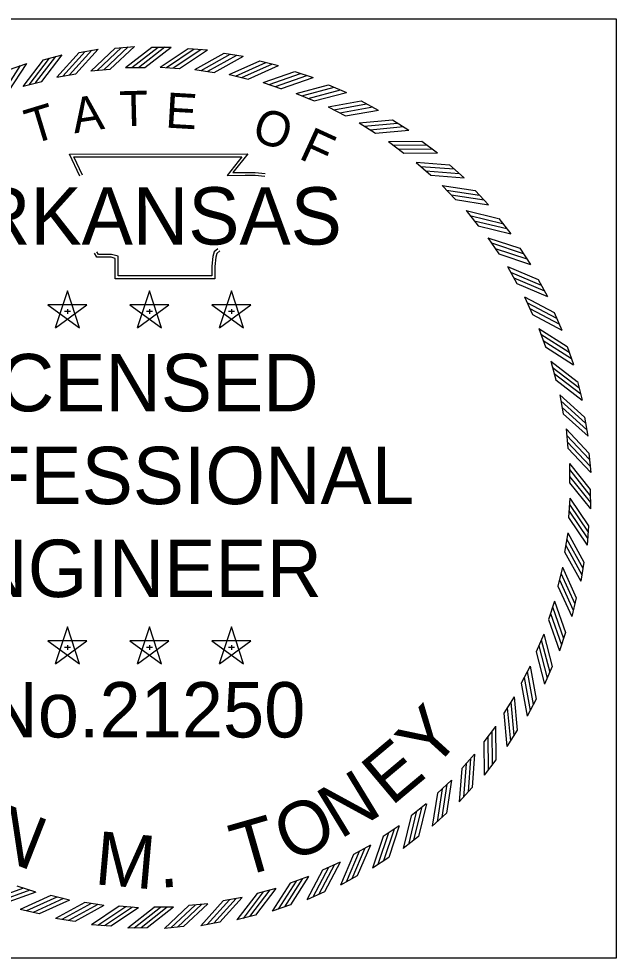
# Model space of a CAD drawing. Extents: x 0 to 1228740, y 0 to 152440.
# Drawn here: x 35.456 to 37.204, y 22.732 to 25.482 of the extents above; entities that cross this region are included whole.
import ezdxf

# ---------------------------------------------------------------- set-up
doc = ezdxf.new("R2010")
doc.units = 0
doc.layers.add('STAMP_JMT', color=7, linetype='Continuous')

msp = doc.modelspace()

# ---------------------------------------------------------------- linework, layer by layer
at = {"layer": 'STAMP_JMT'}
for p, q in [((35.6326, 25.3832), (35.6883, 25.3931)), ((35.7384, 25.3959), (35.7948, 25.4011)), ((35.8455, 25.399), (35.9021, 25.399)), ((35.9515, 25.3948), (36.0079, 25.3907)), ((35.5282, 25.3619), (35.5829, 25.3763)), ((36.0572, 25.3811), (36.113, 25.3723)), ((36.1614, 25.3587), (36.2163, 25.3453)), ((35.4258, 25.332), (35.4792, 25.3509)), ((35.6671, 25.3289), (35.7236, 25.3341)), ((35.7684, 25.3389), (35.825, 25.3389)), ((35.8701, 25.3405), (35.9266, 25.3363)), ((35.9716, 25.3336), (36.0276, 25.3248)), ((36.2634, 25.3277), (36.317, 25.3099)), ((35.5671, 25.3106), (35.6229, 25.3204)), ((36.0722, 25.3185), (36.1272, 25.3051)), ((35.4688, 25.2841), (35.5237, 25.2985)), ((36.1712, 25.295), (36.2249, 25.2771)), ((36.3625, 25.2885), (36.4145, 25.2662)), ((36.2679, 25.2635), (36.32, 25.2412)), ((36.3617, 25.2241), (36.4118, 25.1976)), ((36.458, 25.2412), (36.508, 25.2147)), ((36.4519, 25.1771), (36.4996, 25.1465)), ((36.5493, 25.1861), (36.5969, 25.1557)), ((36.5379, 25.1228), (36.583, 25.0884)), ((36.6358, 25.1238), (36.6807, 25.0894)), ((36.6191, 25.0615), (36.6612, 25.0235)), ((36.7167, 25.0545), (36.7587, 25.0165)), ((36.6951, 24.9938), (36.7338, 24.9525)), ((36.7917, 24.9787), (36.8304, 24.9374)), ((36.7651, 24.9201), (36.8003, 24.8757)), ((36.8602, 24.897), (36.8954, 24.8527)), ((36.8288, 24.8408), (36.8603, 24.7936)), ((36.9217, 24.8099), (36.9531, 24.7629)), ((36.8858, 24.7565), (36.9132, 24.7069)), ((36.9758, 24.7181), (37.0032, 24.6686)), ((35.5984, 24.6856), (35.563, 24.577)), ((35.6337, 24.5771), (35.5985, 24.6857)), ((35.8383, 24.6856), (35.8029, 24.577)), ((35.8735, 24.5771), (35.8384, 24.6857)), ((36.0782, 24.6856), (36.0428, 24.577)), ((36.1134, 24.5771), (36.0782, 24.6857)), ((36.9356, 24.6678), (36.9589, 24.6161)), ((35.6555, 24.6441), (35.5413, 24.6442)), ((35.5414, 24.6441), (35.6337, 24.5769)), ((35.5632, 24.5771), (35.6556, 24.6441)), ((35.8953, 24.6441), (35.7812, 24.6442)), ((35.7813, 24.6441), (35.8736, 24.5769)), ((35.803, 24.5771), (35.8955, 24.6441)), ((36.1352, 24.6441), (36.021, 24.6442)), ((36.0211, 24.6441), (36.1134, 24.5769)), ((36.0429, 24.5771), (36.1353, 24.6441)), ((35.5903, 24.6259), (35.6073, 24.6259)), ((35.5985, 24.632), (35.5985, 24.6177)), ((35.8302, 24.6259), (35.8471, 24.6259)), ((35.8384, 24.632), (35.8384, 24.6177)), ((36.07, 24.6259), (36.087, 24.6259)), ((36.0783, 24.632), (36.0783, 24.6177)), ((37.0221, 24.6221), (37.0453, 24.5705)), ((36.9779, 24.5753), (36.9968, 24.5218)), ((37.0604, 24.5226), (37.0792, 24.4693)), ((37.0124, 24.4796), (37.0269, 24.4248)), ((37.0903, 24.4203), (37.1047, 24.3656)), ((37.039, 24.3814), (37.0488, 24.3255)), ((37.1116, 24.3158), (37.1214, 24.2601)), ((37.0573, 24.2813), (37.0625, 24.2249)), ((37.1243, 24.21), (37.1295, 24.1537)), ((37.0672, 24.1801), (37.0678, 24.1234)), ((37.1281, 24.1034), (37.1286, 24.0469)), ((37.0688, 24.0783), (37.0647, 24.0218)), ((37.1232, 23.997), (37.119, 23.9406)), ((37.062, 23.9768), (37.0532, 23.9208)), ((37.0468, 23.8763), (37.0334, 23.8212)), ((37.1095, 23.8913), (37.1007, 23.8354)), ((37.0234, 23.7773), (37.0055, 23.7235)), ((37.087, 23.787), (37.0737, 23.7321)), ((35.5984, 23.7021), (35.563, 23.5935)), ((35.6337, 23.5936), (35.5985, 23.7022)), ((35.8383, 23.7021), (35.8029, 23.5935)), ((35.8735, 23.5936), (35.8384, 23.7022)), ((36.0782, 23.7021), (36.0428, 23.5935)), ((36.1134, 23.5936), (36.0782, 23.7022)), ((36.9919, 23.6805), (36.9696, 23.6284)), ((37.0561, 23.685), (37.0382, 23.6314)), ((35.6555, 23.6606), (35.5413, 23.6607)), ((35.5414, 23.6606), (35.6337, 23.5934)), ((35.5632, 23.5936), (35.6556, 23.6606)), ((35.8953, 23.6606), (35.7812, 23.6607)), ((35.7813, 23.6606), (35.8736, 23.5934)), ((35.803, 23.5936), (35.8955, 23.6606)), ((36.1352, 23.6606), (36.021, 23.6607)), ((36.0211, 23.6606), (36.1134, 23.5934)), ((36.0429, 23.5936), (36.1353, 23.6606)), ((35.5903, 23.6424), (35.6073, 23.6424)), ((35.5985, 23.6485), (35.5985, 23.6341)), ((35.8302, 23.6424), (35.8471, 23.6424)), ((35.8384, 23.6485), (35.8384, 23.6341)), ((36.07, 23.6424), (36.087, 23.6424)), ((36.0783, 23.6485), (36.0783, 23.6341)), ((36.9525, 23.5868), (36.9259, 23.5367)), ((37.0169, 23.5859), (36.9946, 23.5339)), ((36.9054, 23.4965), (36.8749, 23.4488)), ((36.9695, 23.4904), (36.9431, 23.4404)), ((36.8511, 23.4105), (36.8167, 23.3655)), ((36.9145, 23.3991), (36.884, 23.3515)), ((36.7899, 23.3293), (36.7519, 23.2872)), ((36.8521, 23.3127), (36.8178, 23.2677)), ((36.7222, 23.2534), (36.6808, 23.2146)), ((36.7828, 23.2317), (36.7449, 23.1897)), ((36.6484, 23.1833), (36.604, 23.1481)), ((36.7071, 23.1567), (36.6658, 23.118)), ((36.5691, 23.1196), (36.522, 23.0881)), ((36.6254, 23.0882), (36.5811, 23.0531)), ((36.4849, 23.0626), (36.4353, 23.0352)), ((36.5383, 23.0267), (36.4912, 22.9953)), ((36.3962, 23.0128), (36.3445, 22.9896)), ((36.3036, 22.9705), (36.2502, 22.9516)), ((36.4465, 22.9726), (36.397, 22.9452)), ((35.5056, 22.925), (35.4518, 22.9429)), ((36.2079, 22.936), (36.1531, 22.9216)), ((35.6046, 22.9016), (35.5495, 22.915)), ((36.1097, 22.9095), (36.0539, 22.8996)), ((36.3504, 22.9263), (36.2989, 22.9031)), ((35.7052, 22.8864), (35.6492, 22.8952)), ((35.8067, 22.8796), (35.7502, 22.8838)), ((35.9084, 22.8812), (35.8517, 22.8807)), ((36.0097, 22.8912), (35.9532, 22.886)), ((36.2509, 22.888), (36.1976, 22.8692)), ((35.5154, 22.8614), (35.4605, 22.8748)), ((36.1486, 22.8581), (36.0939, 22.8438)), ((35.6196, 22.839), (35.5638, 22.8478)), ((35.7253, 22.8252), (35.6689, 22.8294)), ((36.0442, 22.8368), (35.9885, 22.827)), ((35.8318, 22.8203), (35.7753, 22.8198)), ((35.9383, 22.8242), (35.882, 22.819))]:
    msp.add_line(p, q, dxfattribs=at)
msp.add_lwpolyline([(34.454, 25.4817), (37.204, 25.4817), (37.204, 22.7317), (34.454, 22.7317)], close=True, dxfattribs=at)
for points in [[(35.567, 25.3105), (35.6325, 25.3832)], [(35.585, 25.3135), (35.6505, 25.3862)], [(35.6042, 25.3174), (35.6698, 25.39)], [(35.6228, 25.3205), (35.6883, 25.3931)], [(35.6671, 25.3288), (35.7384, 25.3958)], [(35.6852, 25.3303), (35.7565, 25.3973)], [(35.7047, 25.3326), (35.776, 25.3996)], [(35.7235, 25.3341), (35.7948, 25.4011)], [(35.7683, 25.3388), (35.8455, 25.399)], [(35.7865, 25.3387), (35.8637, 25.3988)], [(35.8061, 25.3391), (35.8833, 25.3993)], [(35.825, 25.3389), (35.9021, 25.3991)], [(35.87, 25.3404), (35.9514, 25.3948)], [(35.8881, 25.3389), (35.9695, 25.3933)], [(35.9078, 25.3379), (35.9891, 25.3922)], [(35.9265, 25.3363), (36.0079, 25.3907)], [(35.4688, 25.284), (35.5281, 25.3618)], [(35.4864, 25.2885), (35.5457, 25.3663)], [(35.5053, 25.2939), (35.5646, 25.3717)], [(35.5236, 25.2985), (35.5829, 25.3763)], [(35.9715, 25.3336), (36.0571, 25.381)], [(35.9895, 25.3306), (36.075, 25.378)], [(36.0089, 25.328), (36.0945, 25.3754)], [(36.0275, 25.3249), (36.1131, 25.3723)], [(36.0721, 25.3184), (36.1613, 25.3586)], [(35.4087, 25.2623), (35.4614, 25.3448)], [(35.4265, 25.2685), (35.4792, 25.3509)], [(36.0897, 25.314), (36.1789, 25.3542)], [(36.1089, 25.3097), (36.1981, 25.35)], [(36.1272, 25.3051), (36.2164, 25.3453)], [(36.1711, 25.295), (36.2633, 25.3277)], [(36.1883, 25.2891), (36.2805, 25.3218)], [(36.2071, 25.2833), (36.2993, 25.316)], [(36.2249, 25.2772), (36.3171, 25.3099)], [(36.2678, 25.2635), (36.3624, 25.2885)], [(36.2845, 25.2562), (36.3791, 25.2812)], [(36.3027, 25.2488), (36.3973, 25.2738)], [(36.32, 25.2413), (36.4146, 25.2663)], [(36.3616, 25.2241), (36.4579, 25.2412)], [(36.3776, 25.2154), (36.4739, 25.2325)], [(36.3952, 25.2066), (36.4915, 25.2237)], [(36.4117, 25.1976), (36.5081, 25.2147)], [(36.4518, 25.1771), (36.5492, 25.1861)], [(36.467, 25.1671), (36.5645, 25.1762)], [(36.4838, 25.1569), (36.5812, 25.166)], [(36.4996, 25.1466), (36.597, 25.1557)], [(36.5378, 25.1228), (36.6357, 25.1238)], [(36.5522, 25.1116), (36.65, 25.1126)], [(35.6348, 25.0206), (35.6047, 25.0858), (36.1262, 25.0862), (36.0827, 25.0314), (36.1181, 25.0319), (36.1477, 25.0322), (36.1773, 25.029)], [(36.5681, 25.1), (36.6659, 25.101)], [(36.5829, 25.0884), (36.6808, 25.0894)], [(35.6423, 25.024), (35.6176, 25.0776), (36.1091, 25.0779), (36.0654, 25.0229), (36.1182, 25.0236), (36.1473, 25.024), (36.1764, 25.0208)], [(36.6191, 25.0616), (36.7167, 25.0545)], [(36.6325, 25.0492), (36.73, 25.0421)], [(36.6473, 25.0364), (36.7449, 25.0293)], [(36.6612, 25.0236), (36.7588, 25.0165)], [(36.695, 24.9938), (36.7916, 24.9787)], [(36.7073, 24.9804), (36.804, 24.9653)], [(36.7211, 24.9664), (36.8177, 24.9513)], [(36.7338, 24.9526), (36.8305, 24.9374)], [(36.765, 24.9201), (36.8601, 24.897)], [(36.7762, 24.9057), (36.8713, 24.8827)], [(36.7888, 24.8906), (36.8839, 24.8675)], [(36.8003, 24.8757), (36.8954, 24.8527)], [(36.8288, 24.8408), (36.9216, 24.81)], [(36.0388, 24.8084), (36.0279, 24.7995), (36.0241, 24.7855), (36.021, 24.7574), (36.021, 24.7291), (35.7464, 24.7291), (35.7464, 24.7695), (35.7464, 24.7865), (35.7275, 24.7922), (35.6894, 24.7922), (35.6845, 24.7997)], [(36.8387, 24.8256), (36.9316, 24.7947)], [(36.85, 24.8095), (36.9428, 24.7786)], [(36.0441, 24.802), (36.0352, 24.7948), (36.0322, 24.784), (36.0293, 24.7569), (36.0293, 24.7209), (35.7381, 24.7209), (35.7381, 24.7695), (35.7381, 24.7803), (35.7263, 24.784), (35.6849, 24.784), (35.6775, 24.7952)], [(36.8603, 24.7937), (36.9531, 24.7629)], [(36.8857, 24.7565), (36.9757, 24.7181)], [(36.8944, 24.7405), (36.9844, 24.7021)], [(36.9043, 24.7235), (36.9943, 24.6851)], [(36.9132, 24.707), (37.0032, 24.6686)], [(36.9355, 24.6678), (37.0221, 24.6221)], [(36.9428, 24.6512), (37.0294, 24.6055)], [(36.9513, 24.6334), (37.0378, 24.5877)], [(36.9589, 24.6162), (37.0454, 24.5705)], [(36.9778, 24.5753), (37.0603, 24.5226)], [(36.9838, 24.5581), (37.0662, 24.5054)], [(36.9907, 24.5397), (37.0732, 24.487)], [(36.9968, 24.5219), (37.0793, 24.4692)], [(37.0124, 24.4796), (37.0902, 24.4203)], [(37.0168, 24.462), (37.0947, 24.4027)], [(37.0223, 24.4431), (37.1001, 24.3838)], [(37.0269, 24.4248), (37.1047, 24.3655)], [(37.0389, 24.3814), (37.1116, 24.3159)], [(37.0419, 24.3635), (37.1145, 24.2979)], [(37.0457, 24.3442), (37.1184, 24.2787)], [(37.0488, 24.3256), (37.1215, 24.2601)], [(37.0572, 24.2814), (37.1242, 24.21)], [(37.0587, 24.2632), (37.1257, 24.1919)], [(37.0609, 24.2437), (37.1279, 24.1724)], [(37.0625, 24.2249), (37.1295, 24.1536)], [(37.0672, 24.1801), (37.1281, 24.1035)], [(37.0672, 24.1619), (37.1281, 24.0853)], [(37.0678, 24.1423), (37.1287, 24.0657)], [(37.0678, 24.1234), (37.1287, 24.0468)], [(37.0688, 24.0784), (37.1231, 23.997)], [(37.0663, 24.0407), (37.1206, 23.9593)], [(37.0673, 24.0603), (37.1216, 23.9789)], [(37.0647, 24.0219), (37.1191, 23.9405)], [(37.059, 23.959), (37.1064, 23.8734)], [(37.062, 23.9769), (37.1094, 23.8913)], [(37.0563, 23.9395), (37.1038, 23.8539)], [(37.0532, 23.9209), (37.1007, 23.8353)], [(37.0468, 23.8763), (37.087, 23.7871)], [(37.0423, 23.8587), (37.0825, 23.7695)], [(37.0335, 23.8212), (37.0737, 23.732)], [(37.0381, 23.8395), (37.0783, 23.7503)], [(37.0175, 23.7601), (37.0502, 23.6679)], [(37.0234, 23.7773), (37.0561, 23.6851)], [(37.0117, 23.7413), (37.0444, 23.6491)], [(37.0055, 23.7235), (37.0383, 23.6313)], [(36.9919, 23.6806), (37.0168, 23.586)], [(36.9845, 23.664), (37.0095, 23.5693)], [(36.9696, 23.6285), (36.9946, 23.5339)], [(36.9772, 23.6457), (37.0022, 23.5511)], [(36.9438, 23.5708), (36.9609, 23.4745)], [(36.9525, 23.5868), (36.9695, 23.4905)], [(36.935, 23.5533), (36.9521, 23.4569)], [(36.926, 23.5367), (36.9431, 23.4404)], [(36.9054, 23.4966), (36.9145, 23.3992)], [(36.8853, 23.4646), (36.8943, 23.3672)], [(36.8955, 23.4814), (36.9046, 23.384)], [(36.875, 23.4488), (36.884, 23.3514)], [(36.8511, 23.4106), (36.8521, 23.3128)], [(36.8284, 23.3804), (36.8294, 23.2825)], [(36.84, 23.3962), (36.841, 23.2984)], [(36.8168, 23.3655), (36.8178, 23.2677)], [(36.7899, 23.3294), (36.7828, 23.2318)], [(36.7647, 23.3011), (36.7577, 23.2035)], [(36.7776, 23.316), (36.7705, 23.2184)], [(36.752, 23.2872), (36.7449, 23.1897)], [(36.7088, 23.2411), (36.6937, 23.1444)], [(36.7222, 23.2534), (36.7071, 23.1568)], [(36.6809, 23.2146), (36.6658, 23.1179)], [(36.6948, 23.2274), (36.6797, 23.1307)], [(36.6485, 23.1834), (36.6254, 23.0883)], [(36.619, 23.1597), (36.5959, 23.0646)], [(36.6341, 23.1722), (36.611, 23.0771)], [(36.6041, 23.1481), (36.5811, 23.053)], [(36.5539, 23.1097), (36.5231, 23.0168)], [(36.5692, 23.1197), (36.5383, 23.0268)], [(36.5221, 23.0881), (36.4912, 22.9953)], [(36.5378, 23.0985), (36.507, 23.0056)], [(36.4689, 23.054), (36.4305, 22.964)], [(36.4849, 23.0627), (36.4465, 22.9727)], [(36.4353, 23.0352), (36.3969, 22.9452)], [(36.4519, 23.0441), (36.4135, 22.9541)], [(36.3618, 22.9971), (36.3161, 22.9106)], [(36.3795, 23.0056), (36.3338, 22.9191)], [(36.3962, 23.0129), (36.3505, 22.9264)], [(36.2865, 22.9647), (36.2338, 22.8822)], [(36.3037, 22.9706), (36.251, 22.8881)], [(36.3445, 22.9896), (36.2988, 22.903)], [(35.4697, 22.9368), (35.3775, 22.904)], [(36.208, 22.936), (36.1487, 22.8582)], [(36.2503, 22.9516), (36.1976, 22.8691)], [(36.2681, 22.9577), (36.2154, 22.8752)], [(35.4885, 22.931), (35.3963, 22.8982)], [(35.5057, 22.9251), (35.4135, 22.8923)], [(35.5496, 22.9149), (35.4604, 22.8747)], [(35.5679, 22.9103), (35.4787, 22.8701)], [(36.1098, 22.9095), (36.0443, 22.8369)], [(36.1532, 22.9215), (36.0939, 22.8437)], [(36.1715, 22.9262), (36.1122, 22.8483)], [(36.1904, 22.9316), (36.131, 22.8537)], [(35.5871, 22.9061), (35.4979, 22.8659)], [(35.6047, 22.9016), (35.5155, 22.8614)], [(35.6493, 22.8952), (35.5637, 22.8477)], [(35.6679, 22.8921), (35.5823, 22.8446)], [(35.6873, 22.8894), (35.6018, 22.842)], [(35.7053, 22.8865), (35.6197, 22.839)], [(35.7502, 22.8837), (35.6689, 22.8294)], [(35.769, 22.8822), (35.6877, 22.8278)], [(35.7886, 22.8811), (35.7073, 22.8268)], [(35.8518, 22.8806), (35.7752, 22.8197)], [(35.8707, 22.8806), (35.7941, 22.8197)], [(35.8903, 22.8812), (35.8137, 22.8203)], [(35.9085, 22.8812), (35.8319, 22.8203)], [(35.9533, 22.8859), (35.882, 22.8189)], [(35.9721, 22.8875), (35.9008, 22.8205)], [(35.9916, 22.8897), (35.9203, 22.8227)], [(36.0097, 22.8912), (35.9384, 22.8242)], [(36.054, 22.8996), (35.9885, 22.8269)], [(36.0726, 22.9027), (36.007, 22.83)], [(36.0918, 22.9065), (36.0263, 22.8339)], [(35.8068, 22.8796), (35.7254, 22.8253)]]:
    msp.add_lwpolyline(points, dxfattribs=at)

# ---------------------------------------------------------------- texts
for s, height, rotation, p in [('A', 0.1029, 8.6788, (35.6189, 25.1461)), ('T', 0.1029, 1.4789, (35.7518, 25.1666)), ('E', 0.1029, 356.672, (35.8835, 25.1635)), ('T', 0.1029, 16.9015, (35.494, 25.1135)), ('O', 0.1029, 341.2218, (36.1333, 25.1282)), ('F', 0.1029, 335.3628, (36.2719, 25.074)), ('Y', 0.1562, 47.6746, (36.6644, 23.2773)), ('E', 0.1562, 40.0321, (36.5463, 23.1748)), ('N', 0.1562, 31.2978, (36.3961, 23.0782)), ('O', 0.1562, 23.2914, (36.2469, 23.0106)), ('N', 0.1562, 338.5282, (35.3542, 23.0417)), ('T', 0.1562, 16.0128, (36.1043, 22.9677)), ('M', 0.1562, 354.905, (35.6751, 22.9485)), ('.', 0.1562, 4.3671, (35.8682, 22.9375))]:
    msp.add_text(s, height=height, rotation=rotation, dxfattribs=at).set_placement(p)
for s, height, p in [('ARKANSAS', 0.16791, (35.1784, 24.8208)), ('LICENSED', 0.16791, (35.2103, 24.3327)), ('PROFESSIONAL', 0.167907, (34.8665, 24.0609)), ('ENGINEER', 0.16791, (35.1704, 23.789)), ('No.21250', 0.16191, (35.3555, 23.378))]:
    msp.add_text(s, height=height, dxfattribs=at).set_placement(p)

doc.saveas('drawing.dxf')
